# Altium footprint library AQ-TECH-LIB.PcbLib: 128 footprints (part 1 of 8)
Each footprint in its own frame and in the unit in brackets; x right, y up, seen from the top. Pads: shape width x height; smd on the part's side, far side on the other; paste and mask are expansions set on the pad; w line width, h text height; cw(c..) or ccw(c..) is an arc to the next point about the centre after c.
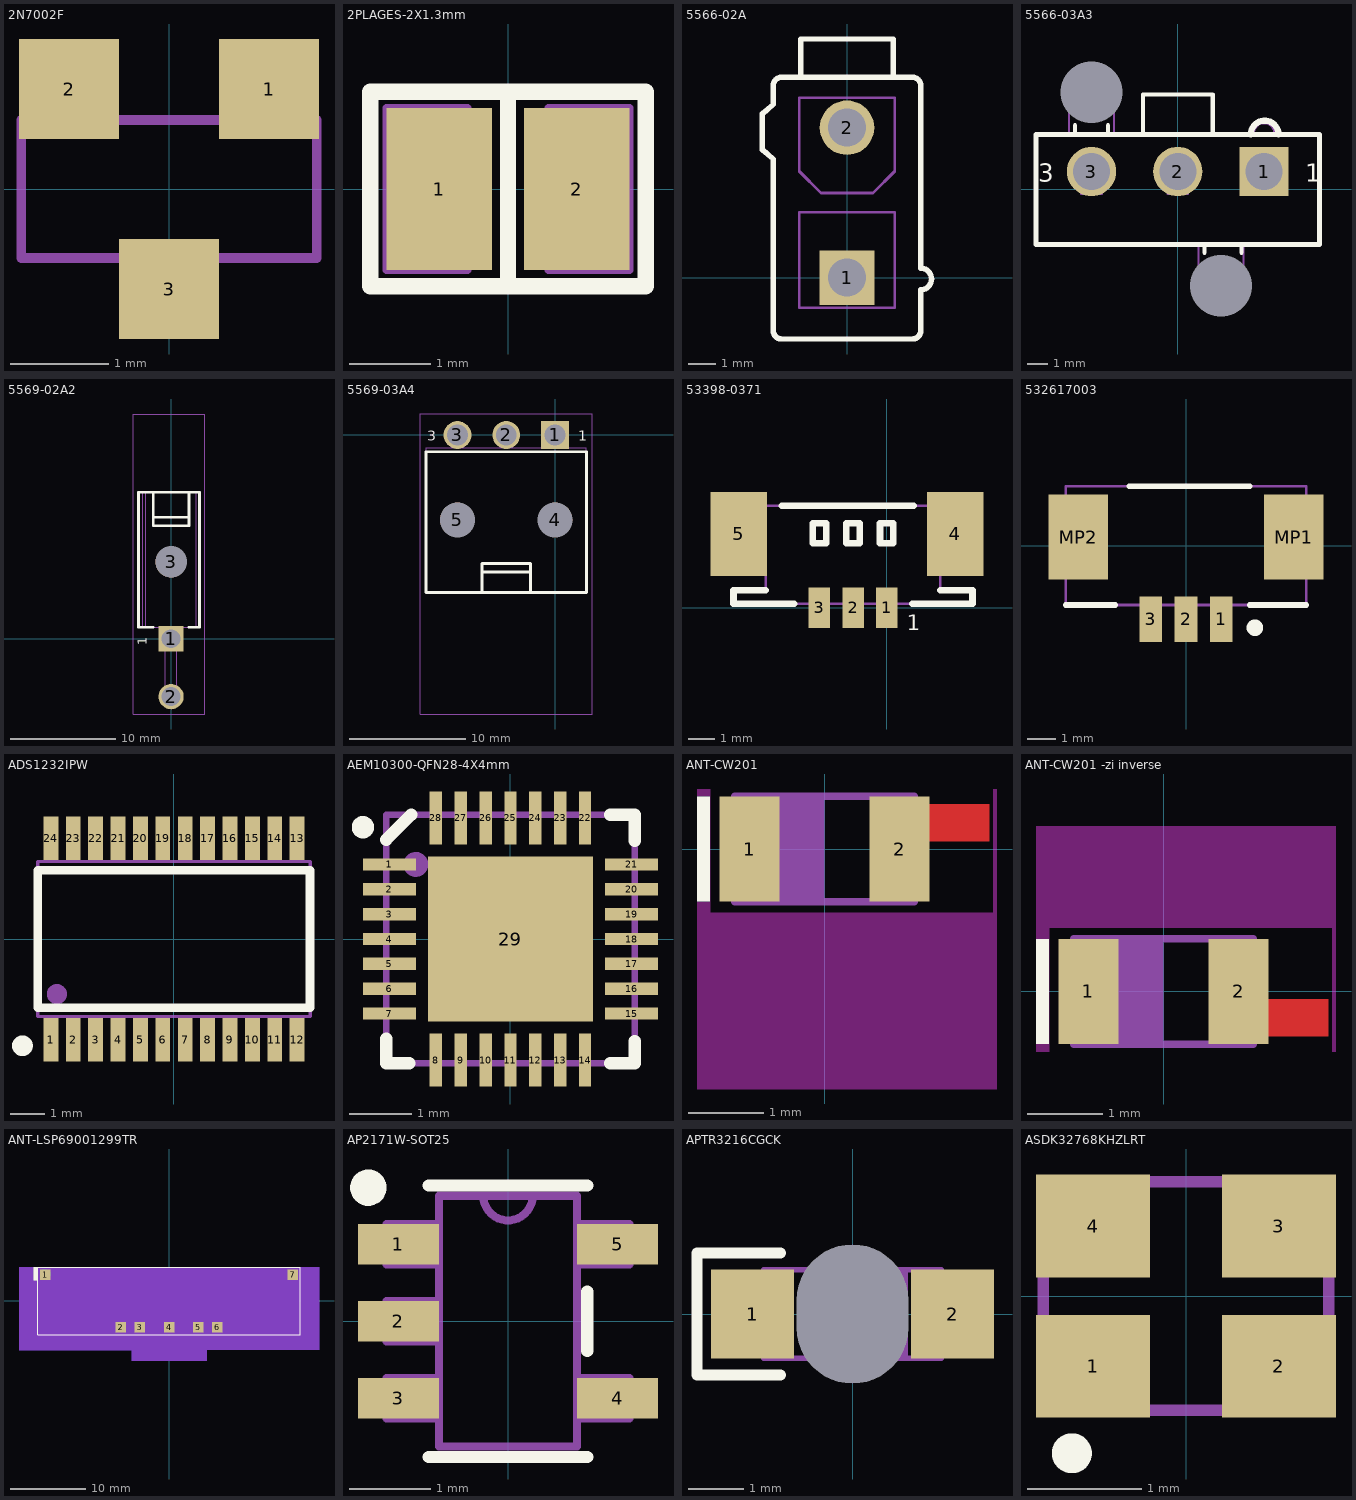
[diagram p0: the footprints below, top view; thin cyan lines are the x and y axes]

## 2N7002F [mil]
height 44.09
pads (3):
  rect 40x40 smd: 1(40,40) 2(-40,40) 3(0,-40)
Mechanical 3:
  lines w3.94: -59.1,-27.6 -59.1,27.6 -47,27.6 -47,49.2 -28,49.2 -28,27.6 28,27.6 28,49.2 47,49.2 47,27.6 59.1,27.6 59.1,-27.6 9.5,-27.6 9.5,-49.2 -9.5,-49.2 -9.5,-27.6 -59.1,-27.6
  text ".Designator" at -28,-21.65 h33.07
3D body "Conception1.stp": height 43.31, standoff 0, extent -59.05,-49.21 59.06,49.22

## 2PLAGES-2X1.3mm [mm]
pads (2):
  rect 1.3x2 smd paste-3 mask+0.1: 1(-0.85,0) 2(0.85,0)
Top Overlay:
  lines w0.2: 0,-1.2 0,1.2 ; -1.7,-1.2 -1.7,1.2 1.7,1.2 1.7,-1.2 -1.7,-1.2
Mechanical 3:
  lines w0.1: -1.5,-1 -0.5,-1 -0.5,1 -1.5,1 -1.5,-1 ; 0.5,-1 1.5,-1 1.5,1 0.5,1 0.5,-1
  text ".Designator" at -1,-0.375 h0.84

## 5566-02A [mm] "MOLEX 38-28-1023"
height 13.1
pads (2):
  rect 2x2 hole 1.4 mask+0.1: 1(0,0)
  round 2 hole 1.4 mask+0.1: 2(0,5.5)
Top Overlay:
  lines w0.2: -1.7,7.35 -1.7,8.75 1.7,8.75 1.7,7.35 ; -3.1,4.686 -3.1,6.014 -2.7,6.35 -2.7,7.05 cw(c-2.4,7.05) -2.4,7.35 2.4,7.35 cw(c2.4,7.05) 2.7,7.05 2.7,0.35 cw(c2.7,-0.05) 3.1,-0.05 cw(c2.7,-0.05) 2.7,-0.45 2.7,-1.95 cw(c2.4,-1.95) 2.4,-2.25 -2.4,-2.25 cw(c-2.4,-1.95) -2.7,-1.95 -2.7,4.35 -3.1,4.686
Mechanical 3:
  lines w0.1: -1.7,7.35 -1.7,8.75 1.7,8.75 1.7,7.35 ; -3.1,4.686 -3.1,6.014 -2.7,6.35 -2.7,7.05 cw(c-2.4,7.05) -2.4,7.35 2.4,7.35 cw(c2.4,7.05) 2.7,7.05 2.7,0.35 cw(c2.7,-0.05) 3.1,-0.05 cw(c2.7,-0.05) 2.7,-0.45 2.7,-1.95 cw(c2.4,-1.95) 2.4,-2.25 -2.4,-2.25 cw(c-2.4,-1.95) -2.7,-1.95 -2.7,4.35 -3.1,4.686 ; -1.75,-1.1 1.75,-1.1 1.75,2.4 -1.75,2.4 -1.75,-1.1 ; -1.75,3.9 -0.95,3.1 0.95,3.1 1.75,3.9 1.75,6.6 -1.75,6.6 -1.75,3.9
  text ".Designator" at 0,3 h0.84
  text "1" at -0.2,0.1 h0.84
  text "2" at -0.4,4.2 h0.84
3D body "39281023.stp": height 12.8, standoff -3.5, extent -3.1,-2.225 3.1,8.775

## 5566-03A3 [mm]
height 12.45
pads (5):
  rect 2.4x2.4 hole 1.8: 1(4.2,0.85)
  round 2.4 hole 1.8: 2(0,0.85) 3(-4.2,0.85)
  round 0 hole 3 unplated mask+1.6: 4(2.1,-4.7) 5(-4.2,4.7)
Top Overlay:
  lines w0.2: -5,2.7 -5,3.1 ; -3.4,2.7 -3.4,3.1 ; -1.7,2.65 -1.7,4.6 1.7,4.6 1.7,2.7 ; 1.3,-3.1 1.3,-2.7 ; 3.1,-3.1 3.1,-2.7
  lines w0.25: -1.7,2.65 1.7,2.65 ; -6.9,-2.7 6.9,-2.7 6.9,2.65 -6.9,2.65 -6.9,-2.7
  lines w0.3: 3.55,2.65 cw(c4.227,2.65) 4.904,2.65
  text "1" at 6.2,0.05 h1.5
  text "3" at -6.8,0.05 h1.5
Mechanical 3:
  lines w0.1: -5.3,2.7 -5.3,5.6 -3.1,5.6 -3.1,2.7 ; 1,-2.7 1,-5.6 3.2,-5.6 3.2,-2.7 ; 3.7,2.7 cw(c4.2,2.7) 4.7,2.7 ; -6.9,-2.7 -6.9,2.7 6.9,2.7 6.9,-2.7 -6.9,-2.7 ; -4.7,-0.25 -4.7,0.85 -3.7,0.85 -3.7,-0.25 -4.7,-0.25 ; -1.7,2.7 1.7,2.7 1.7,4.6 -0.1,4.6 -1.7,4.6 -1.7,2.7 ; -0.5,-0.25 -0.5,0.85 0.5,0.85 0.5,-0.25 -0.5,-0.25 ; 3.7,-0.25 3.7,0.85 4.7,0.85 4.7,-0.25 3.7,-0.25
  text ".Designator" at -2.9,-1.3 h0.84
  text "3" at -6.5,0.35 h0.84
  text "1" at 6,0.35 h0.84
3D body "39301039.stp": height 12.45, standoff -3.5, extent -6.9,-5.779 6.9,5.779

## 5569-02A2 [mm]
height 11.4
pads (3):
  rect 2.4x2.4 hole 1.8 mask+0.1: 1(0,0)
  round 2.4 hole 1.8 mask+0.1: 2(0,-5.5)
  round 2.97 hole 3 unplated mask+0.2: 3(0,7.3)
Top Overlay:
  lines w0.25: -1.7,1.1 -2.75,1.1 -3.1,1.1 -3.1,13.9 2.7,13.9 2.7,1.1 1.7,1.1 ; -1.7,11.55 1.7,11.55 ; -1.7,13.9 -1.7,10.728 1.7,10.728 1.7,13.9
  text "1" at -2.05,-0.6 h1.5
Mechanical 1:
  lines w0.01: -3.6,-7.15 3.2,-7.15 3.2,21.35 -3.6,21.35 -3.6,-7.15
Mechanical 3:
  lines w0.1: -2.7,1.1 -2.7,13.9 ; 0.535,-4.465 0.535,-0.535 ; 1.7,13.9 1.7,11.55 ; 2.4,1.1 2.4,13.9 ; -2.4,1.1 -2.4,13.9 ; -2.4,1.1 2.7,1.1 2.7,13.9 -1.7,13.9 ; -2.4,1.1 -3.1,1.1 -3.1,13.9 -2.4,13.9 ; -2.4,13.9 -1.7,13.9 ; -1.7,11.55 1.7,11.55 ; -1.7,11.55 -1.7,13.9 ; -1.7,11.55 -1.7,10.728 1.7,10.728 1.7,11.55 ; -0.535,-5.5 0.535,-5.5 0.535,1.1 -0.535,1.1 -0.535,-5.5
  text "2" at -1.8,-6 h0.84
  text "1" at -1.55,-0.75 h0.84
  text ".Designator" at 0.125,3.1 h0.84
3D body "026013114.stp": height 11.4, standoff -3.6, extent -3.1,-6.035 2.7,13.9

## 5569-03A4 [mm]
height 7.2
pads (5):
  rect 2.4x2.4 hole 1.8: 1(0,0)
  round 2.4 hole 1.8: 2(-4.2,0) 3(-8.4,0)
  round 2.97 hole 3 unplated: 4(0,-7.3) 5(-8.4,-7.3)
Top Overlay:
  lines w0.25: -6.3,-11.05 -2.1,-11.05 ; -6.3,-11.05 -6.3,-13.55 -2.1,-13.55 -2.1,-11.05 ; -6.3,-11.05 -2.1,-11.05 ; -6.3,-11.05 -6.3,-11.8 -2.1,-11.8 -2.1,-11.05 ; -11.1,-13.55 2.7,-13.55 2.7,-1.45 -11.1,-1.45 -11.1,-13.55
  text "1" at 2,-0.8 h1.5
  text "3" at -11,-0.8 h1.5
Mechanical 1:
  lines w0.01: -11.6,-24 3.2,-24 3.2,1.8 -11.6,1.8 -11.6,-24
Mechanical 3:
  lines w0.1: -6.3,-11.05 -2.1,-11.05 ; -6.3,-11.05 -6.3,-13.55 -2.1,-13.55 -2.1,-11.05 ; -6.3,-11.05 -2.1,-11.05 ; -6.3,-11.05 -6.3,-11.8 -2.1,-11.8 -2.1,-11.05 ; -11.1,-13.55 -11.1,-1.1 2.7,-1.1 2.7,-13.55 -11.1,-13.55 ; -8.9,-1.1 -8.9,0 -7.9,0 -7.9,-1.1 -8.9,-1.1 ; -4.7,-1.1 -4.7,0 -3.7,0 -3.7,-1.1 -4.7,-1.1 ; -0.5,-1.1 -0.5,0 0.5,0 0.5,-1.1 -0.5,-1.1
  text ".Designator" at -8.499,-5.92 h0.84
  text "3" at -10.7,-0.5 h0.84
  text "1" at 1.8,-0.5 h0.84
3D body "039303035.stp": height 7.2, standoff -3.5, extent -11.1,-13.55 2.7,0.535

## 53398-0371 [mm]
height 4.7
pads (5):
  rect 0.8x1.5 smd: 1(0,0) 2(-1.25,0) 3(-2.5,0)
  rect 2.11x3.12 smd: 4(2.55,2.75)
  rect 2.11x3.12 smd paste+0: 5(-5.5,2.75)
Top Overlay:
  lines w0.25: -4.5,0.65 -5.7,0.65 -5.7,0.15 -3.45,0.15 ; -3.9,3.8 1,3.8 ; 0.95,0.15 3.2,0.15 3.2,0.65 2,0.65 ; -2.75,2.4 -2.75,3.15 -2.25,3.15 -2.25,2.4 -2.75,2.4 ; -1.5,2.4 -1.5,3.15 -1,3.15 -1,2.4 -1.5,2.4 ; -0.25,2.4 -0.25,3.15 0.25,3.15 0.25,2.4 -0.25,2.4
  text "1" at 0.75,-1.05 h1
Mechanical 3:
  lines w0.1: -5.7,0.15 -5.7,0.65 -4.5,0.65 -4.5,1.4 -5.7,1.4 -5.7,3.8 3.2,3.8 3.2,1.4 2,1.4 2,0.65 3.2,0.65 3.2,0.15 -5.7,0.15 ; -2.75,2.4 -2.25,2.4 -2.25,3.15 -2.75,3.15 -2.75,2.4 ; -1.5,2.4 -1,2.4 -1,3.15 -1.5,3.15 -1.5,2.4 ; -0.25,2.4 0.25,2.4 0.25,3.15 -0.25,3.15 -0.25,2.4
  text ".Designator" at -1.3,1.6 h0.84
  text "3" at -2.65,0.45 h0.42
  text "1" at -0.05,0.45 h0.42
3D body "533980371.stp": height 4.72, standoff -0.02, extent -5.7,-0.4 3.2,3.8

## 532617003 [mm]
pads (5):
  rect 0.8x1.6 smd: 1(1.25,-2.6) 2(0,-2.6) 3(-1.25,-2.6)
  rect 2.1x3 smd: MP1(3.8,0.3) MP2(-3.8,0.3)
Top Overlay:
  circle w0.5: c2.434,-2.898 r0.041
  lines w0.2: -4.25,-2.1 -2.5,-2.1 ; -2,2.1 2.25,2.1 ; 2.25,-2.1 4.25,-2.1
Mechanical 3:
  lines w0.1: -4.25,-2.1 -4.25,2.1 4.25,2.1 4.25,-2.1 -4.25,-2.1
  text "1" at 1.05,-2.005 h1
  text ".Designator" at -0.025,-0.05 h0.84
3D body "53261-7003.stp": height 3.4, standoff 0, extent -4.45,-3.205 4.45,1.995

## ADS1232IPW [mm]
height 1.2
pads (24):
  rect 0.432x1.27 smd paste+0 mask+0.05: 1(-3.575,-2.925) 2(-2.925,-2.925) 3(-2.275,-2.925) 4(-1.625,-2.925) 5(-0.975,-2.925) 6(-0.325,-2.925) 7(0.325,-2.925) 8(0.975,-2.925) 9(1.625,-2.925) 10(2.275,-2.925) 11(2.925,-2.925) 12(3.575,-2.925) 13(3.575,2.925) 14(2.925,2.925) 15(2.275,2.925) 16(1.625,2.925) 17(0.975,2.925) 18(0.325,2.925) 19(-0.325,2.925) 20(-0.975,2.925) 21(-1.625,2.925) 22(-2.275,2.925) 23(-2.925,2.925) 24(-3.575,2.925)
Top Overlay:
  circle w0.4: c-4.4,-3.1 r0.1
  lines w0.25: -3.95,-2 3.95,-2 3.95,2 -3.95,2 -3.95,-2
Mechanical 3:
  circle w0.3: c-3.4,-1.6 r0.141
  lines w0.1: -3.95,-2.25 -3.95,2.25 3.95,2.25 3.95,-2.25 -3.95,-2.25
  text ".Designator" at 0.9,0.325 h0.84
3D body: height 1.2, standoff 0, extent -3.95,-2.25 3.95,2.25
3D body: height 1.21, standoff 0, extent -3.649,-1.85 -3.151,-1.35

## AEM10300-QFN28-4X4mm [mm]
height 0.85
pads (29):
  rect 0.85x0.2 smd mask+0.05: 1(-1.95,1.2) 2(-1.95,0.8) 3(-1.95,0.4) 4(-1.95,0) 5(-1.95,-0.4) 6(-1.95,-0.8) 7(-1.95,-1.2) 15(1.95,-1.2) 16(1.95,-0.8) 17(1.95,-0.4) 18(1.95,0) 19(1.95,0.4) 20(1.95,0.8) 21(1.95,1.2)
  rect 0.2x0.85 smd mask+0.05: 8(-1.2,-1.95) 9(-0.8,-1.95) 10(-0.4,-1.95) 11(0,-1.95) 12(0.4,-1.95) 13(0.8,-1.95) 14(1.2,-1.95) 22(1.2,1.95) 23(0.8,1.95) 24(0.4,1.95) 25(0,1.95) 26(-0.4,1.95) 27(-0.8,1.95) 28(-1.2,1.95)
  rect 2.65x2.65 smd mask+0.05: 29(0,0)
Top Overlay:
  circle w0.2: c-2.375,1.8 r0.08
  lines w0.2: -2,-1.605 -2,-2 -1.631,-2 ; -2,1.6 -1.6,2 ; 1.608,-2 2,-2 2,-1.642 ; 1.608,2 2,2 2,1.585
Mechanical 3:
  circle w0.2: c-1.525,1.2 r0.1
  lines w0.1: -2,1.6 -1.6,2 ; -2,-2 -2,2 2,2 2,-2 -2,-2
  text ".Designator" at -0.7,-0.4 h0.84
3D body "aem10900.stp": height 0.85, standoff 0, extent -2.05,-2.05 2.05,2.05

## ANT-CW201 [mm] "refusion"
height 0.8
pads (2):
  rect 0.8x1.4 smd: 1(-1,0) 2(1,0)
Top Layer:
  rectangle: 1,0.1 2.2,0.6
Top Overlay:
  rectangle: -1.7,-0.7 -1.525,0.7
Keep-Out Layer:
  region: -1.7,0.8 -1.7,-3.2 2.3,-3.2 2.3,0.8 2.25,0.8 2.25,-0.85 -1.525,-0.85 -1.525,0.8
Mechanical 3:
  rectangle: -0.9,-0.7 0,0.7
  lines w0.1: -0.9,-0.7 -0.9,0.7 -1.2,0.7 ; 0.9,-0.7 0.9,0.7 1.2,0.7 ; -1.2,0.7 1.2,0.7 ; -1.2,0.7 -1.2,-0.7 1.2,-0.7 1.2,0.7
  text ".Designator" at -0.7,-0.4 h0.84
3D body: height 0.8, standoff 0, extent 0.9,-0.7 1.2,0.7
3D body: height 0.8, standoff 0, extent -1.2,-0.7 -0.9,0.7
3D body: height 0.8, standoff 0, extent -0.9,-0.7 0,0.7
3D body: height 0.8, standoff 0, extent -1.2,-0.7 1.2,0.7

## ANT-CW201 -zi inverse [mm] "refusion"
height 0.8
pads (2):
  rect 0.8x1.4 smd: 1(-1,0) 2(1,0)
Top Layer:
  rectangle: 1,-0.6 2.2,-0.1
Top Overlay:
  rectangle: -1.7,-0.7 -1.525,0.7
Keep-Out Layer:
  region: -1.7,-0.8 -1.7,2.2 2.3,2.2 2.3,-0.8 2.25,-0.8 2.25,0.85 -1.525,0.85 -1.525,-0.8
Mechanical 3:
  rectangle: -0.9,-0.7 0,0.7
  lines w0.1: -0.9,-0.7 -0.9,0.7 -1.2,0.7 ; 0.9,-0.7 0.9,0.7 1.2,0.7 ; -1.2,0.7 -1.2,-0.7 1.2,-0.7 1.2,0.7 ; -1.2,0.7 1.2,0.7
  text ".Designator" at -0.7,-0.4 h0.84
3D body: height 0.8, standoff 0, extent -1.2,-0.7 1.2,0.7
3D body: height 0.8, standoff 0, extent -0.9,-0.7 0,0.7
3D body: height 0.8, standoff 0, extent -1.2,-0.7 -0.9,0.7
3D body: height 0.8, standoff 0, extent 0.9,-0.7 1.2,0.7

## ANT-LSP69001299TR [mm]
height 3.2
pads (7):
  rect 1.4x1.4 smd: 1(-16.5,3.5) 2(-6.402,-3.5) 3(-3.9,-3.5) 4(0,-3.5) 5(3.9,-3.5) 6(6.4,-3.5) 7(16.5,3.5)
Top Layer keep-out:
  region: -20,4.5 -20,-6.556 -5.056,-6.556 -5,-6.5 -5,-8 5,-8 5,-6.5 19.992,-6.5 20,-6.508 20,4.5
Bottom Layer keep-out:
  region: -20,4.5 -20,-6.556 -5.056,-6.556 -5,-6.5 -5,-8 5,-8 5,-6.5 19.992,-6.5 20,-6.508 20,4.5
Top Overlay:
  rectangle: -18.05,2.725 -17.5,4.5
  lines w0.125: -17.5,-4.5 -17.5,4.5 17.5,4.5 17.5,-4.5 -17.5,-4.5
Mechanical 3:
  circle w0.2: c-16.5,3.5 r0.702
  lines w0.013: -17.5,-4.5 17.5,-4.5 17.5,4.5 -17.5,4.5 -17.5,-4.5
  lines w0.1: -17.5,-4.5 -17.5,4.5 17.5,4.5 17.5,-4.5 -17.5,-4.5
  text "'.Designator'" at 0,0 h0.8
3D body "LSP69001299TR.stp": height 3.17, standoff 0.03, extent -17.5,-4.5 17.5,4.5

## AP2171W-SOT25 [mm]
height 1.4
pads (5):
  rect 1x0.5 smd: 1(-1.353,0.95) 2(-1.353,0) 3(-1.353,-0.95) 4(1.353,-0.95) 5(1.353,0.95)
Top Overlay:
  circle w0.25: c-1.725,1.65 r0.1
  lines w0.152: -0.977,-1.677 0.977,-1.677 ; -0.977,1.677 0.977,1.677 ; 0.977,-0.367 0.977,0.367
Mechanical 3:
  lines w0.1: -0.305,1.55 ccw(c0,1.55) 0.305,1.55 ; -1.5,-1.2 -0.85,-1.2 -0.85,-0.7 -1.5,-0.7 -1.5,-1.2 ; -1.5,-0.25 -0.85,-0.25 -0.85,0.25 -1.5,0.25 -1.5,-0.25 ; -1.5,0.7 -0.85,0.7 -0.85,1.2 -1.5,1.2 -1.5,0.7 ; -0.85,-1.55 -0.85,1.55 0.85,1.55 0.85,-1.55 -0.85,-1.55 ; 0.85,-1.2 1.5,-1.2 1.5,-0.7 0.85,-0.7 0.85,-1.2 ; 0.85,0.7 1.5,0.7 1.5,1.2 0.85,1.2 0.85,0.7
  text ".Designator" at 0.4,-1.125 h0.84
3D body "SOT25_DIO.step": height 1.45, standoff 0, extent -1.5,-1.55 1.5,1.55

## APTR3216CGCK [mm] "LED VERTE"
height 0.55
pads (3):
  round 0 hole 2 slot 2.5 at 90 deg unplated: 0(0,0)
  rect 1.5x1.6 smd: 1(-1.8,0) 2(1.8,0)
Top Overlay:
  lines w0.2: -1.3,-1.1 -2.8,-1.1 -2.8,1.1 -1.3,1.1
Mechanical 3:
  rectangle: -0.8,-0.2 0.8,0.2
  rectangle: 0.4,-0.8 1,0.8
  lines w0.1: -1.6,-0.8 1.6,-0.8 1.6,0.8 -1.6,0.8 -1.6,-0.8
  text "'.Designator'" at -2.1,1.1 h0.8
  text "K" at -1.7,-0.5 h0.8
3D body "APTR3216.STEP": height 0.24, standoff -0.81, extent -1.6,-0.8 1.6,0.8

## ASDK32768KHZLRT [mm]
pads (4):
  rect 1x0.9 smd: 1(-0.813,-0.613) 2(0.813,-0.613) 3(0.813,0.613) 4(-0.813,0.613)
Top Overlay:
  circle w0.25: c-1,-1.375 r0.05
Mechanical 3:
  circle w0.2: c-0.813,-0.613 r0.1
  lines w0.1: -1.25,-1 -1.25,1 1.25,1 1.25,-1 -1.25,-1
  text "'.Designator'" at -0.8,0 h0.8
3D body "ASDK-32.768KHZ-LRT.stp": height 1.05, standoff 0, extent -1.25,-1 1.25,1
